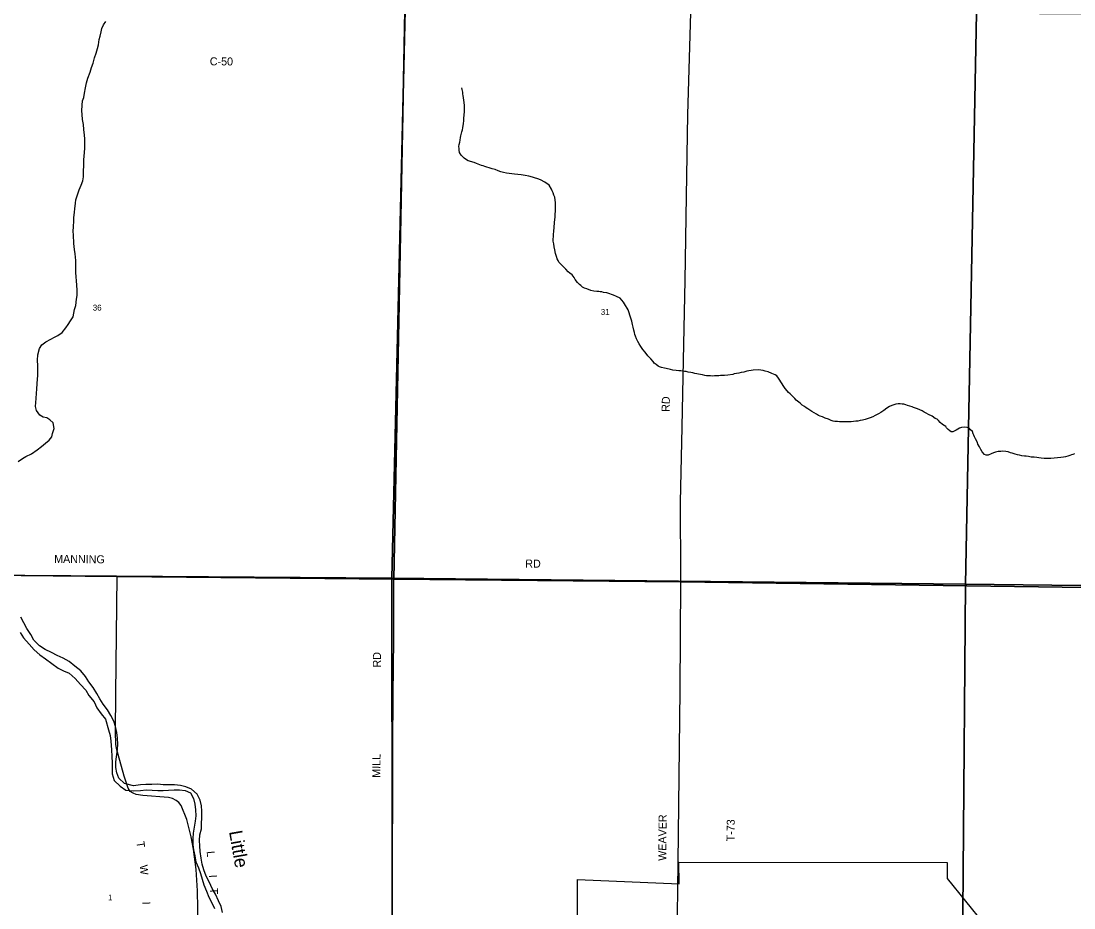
# Model space of a CAD drawing. Extents: x 1312308 to 1684953, y 460642 to 865172.
# Drawn here: x 1439573 to 1449426, y 606234 to 614530 of the extents above; entities that cross this region are included whole.
import ezdxf

# ---------------------------------------------------------------- set-up
doc = ezdxf.new("R2010")
doc.units = 0
for name, color, linetype in [('GM_X_City_Street', 7, 'Continuous'), ('GM_X_Corporation', 7, 'Continuous'), ('GM_X_County_Road', 7, 'Continuous'), ('GM_X_County_Road_Text', 7, 'Continuous'), ('GM_X_Minor_River', 7, 'Continuous'), ('GM_X_Minor_River_Text', 7, 'Continuous'), ('GM_X_Section', 7, 'Continuous'), ('GM_X_Section_Text', 7, 'Continuous'), ('GM_X_Township', 7, 'Continuous'), ('GM_X_Township_Road', 7, 'Continuous'), ('GM_X_Township_Road_Text', 7, 'Continuous')]:
    doc.layers.add(name, color=color, linetype=linetype)

msp = doc.modelspace()

# ---------------------------------------------------------------- linework, layer by layer
at = {"layer": 'GM_X_City_Street'}
msp.add_lwpolyline([(1445695, 601190), (1445690.3, 601641.1), (1445694, 602252.8), (1445695, 602859.2), (1445704.3, 604917.1), (1445707.2, 605261.4), (1445712.1, 605558.2), (1445716.6, 606177.5), (1445719.5, 606404.3), (1445724, 606661.2)], dxfattribs=at)
at = {"layer": 'GM_X_Corporation'}
msp.add_lwpolyline([(1444781.9, 604348.3), (1444781.9, 606501.4), (1445732.6, 606460.3), (1445728.1, 606661.5), (1448239.7, 606658.7), (1448239.7, 606508.7), (1449269.8, 605237)], dxfattribs=at)
at = {"layer": 'GM_X_County_Road'}
for points in [[(1443043.6, 606030.9), (1443047.9, 606430.2), (1443048.8, 606768.8), (1443052.3, 607267), (1443052.3, 607749.7), (1443055.7, 608228.8), (1443060.1, 608745.3), (1443062.5, 609310), (1443164.3, 614625), (1443262.6, 619245.4), (1443279.1, 619936.6), (1443383.2, 625252.4), (1443487.4, 629689.1)], [(1434197.2, 609392.5), (1435199.7, 609380.4), (1437771.4, 609361.5), (1440472, 609335.1), (1443062.5, 609310)], [(1443062.5, 609310), (1445748.3, 609283.3), (1452218.2, 609194.8), (1453789.9, 609169.6)]]:
    msp.add_lwpolyline(points, dxfattribs=at)
at = {"layer": 'GM_X_Minor_River'}
for points in [[(1440169.7, 613427.7), (1440166.4, 613461.8), (1440161.5, 613516.1), (1440156.4, 613562.4), (1440149.4, 613608.7), (1440146.3, 613654.9), (1440141, 613691.1), (1440144.1, 613743.2), (1440148.9, 613783.3), (1440159.6, 613815.2), (1440166.5, 613857.2), (1440177.5, 613905.2), (1440184.5, 613953.2), (1440197.4, 613995.1), (1440218.6, 614050.9), (1440231.5, 614094.9), (1440248.4, 614136.7), (1440261.5, 614186.6), (1440276.4, 614228.5), (1440289.3, 614272.4), (1440296.1, 614308.4), (1440305.1, 614358.4), (1440311.8, 614390.4), (1440322.6, 614428.4), (1440329.3, 614460.4), (1440344, 614494.2), (1440364.7, 614526)], [(1443718, 613614.2), (1443719.1, 613656.4), (1443721.7, 613676.5), (1443722.7, 613716.7), (1443721.3, 613740.9), (1443720, 613767), (1443716.6, 613791.2), (1443713.1, 613813.4), (1443711.6, 613833.6), (1443708, 613847.8), (1443706.4, 613863.9), (1443701, 613890.2), (1443697.4, 613906.3)], [(1445219.1, 611884.9), (1445211.4, 611899.2), (1445180.2, 611938.2), (1445144.4, 611953.1), (1445118.6, 611965.8), (1445098.6, 611972.3), (1445082.7, 611978.7), (1445054.8, 611989.4), (1445024.6, 611992.2), (1445008.7, 611996.6), (1444992.6, 611997), (1444978.5, 611999.3), (1444962.4, 611999.7), (1444932.3, 612002.5), (1444904.4, 612011.2), (1444866.5, 612024.2), (1444846.5, 612030.7), (1444828.7, 612041.2), (1444812.9, 612055.6), (1444799.1, 612066), (1444781.5, 612084.5), (1444760, 612111.2), (1444748.5, 612131.6), (1444731, 612156.1), (1444707.3, 612172.8), (1444693.5, 612185.2), (1444669.9, 612207.8), (1444656.3, 612226.3), (1444642.5, 612236.7), (1444607.2, 612273.7), (1444599.6, 612290), (1444590, 612306.3), (1444582.5, 612328.6), (1444575.2, 612356.9), (1444567.9, 612389.2), (1444560.7, 612419.6), (1444557.4, 612447.8), (1444554, 612472), (1444555.6, 612534.3), (1444558.4, 612564.4), (1444561.3, 612600.5), (1444564.5, 612644.7), (1444569.9, 612698.8), (1444570.7, 612731), (1444573.2, 612747), (1444574.1, 612781.2), (1444574.6, 612801.3), (1444573, 612819.4), (1444573.4, 612833.5), (1444569.9, 612853.7), (1444568.6, 612881.8), (1444559.1, 612902.2), (1444551.6, 612924.5), (1444542, 612942.8), (1444536.4, 612959), (1444515.1, 612993.7), (1444473.6, 613022.9), (1444433.9, 613043.9), (1444408, 613054.6), (1444378.1, 613063.4), (1444358.1, 613069.9), (1444326.1, 613078.7), (1444292.1, 613085.6), (1444254, 613092.5), (1444191.8, 613098.1), (1444165.7, 613100.7), (1444115.5, 613107.9), (1444087.5, 613114.7), (1444063.6, 613121.3), (1444037.6, 613129.9), (1444009.7, 613140.7), (1443981.7, 613147.4), (1443953.8, 613156.1), (1443931.8, 613162.7), (1443913.8, 613169.1), (1443897.9, 613175.5), (1443881.9, 613180), (1443850, 613192.8), (1443836.1, 613197.2), (1443814.1, 613205.7), (1443758.2, 613223.2), (1443740.3, 613231.6), (1443720.6, 613248.2), (1443706.9, 613260.6), (1443693.2, 613275), (1443675.7, 613301.6), (1443672.2, 613321.8), (1443672.6, 613337.8), (1443671.1, 613356), (1443673.6, 613374), (1443678.2, 613396), (1443682.7, 613416), (1443685.4, 613442.1), (1443687.8, 613458.1), (1443696.8, 613494.1), (1443703.4, 613514), (1443707.9, 613532), (1443710.4, 613554.1), (1443712.8, 613568.1), (1443715.7, 613600.2), (1443718, 613614.2)], [(1439546.3, 610409.3), (1439584.9, 610436.7), (1439617.4, 610456.1), (1439670.1, 610481.2), (1439725, 610520.4), (1439765.7, 610549.7), (1439800.5, 610581.2), (1439835.2, 610610.6), (1439859.9, 610642.3), (1439866.5, 610672.2), (1439881.6, 610720.1), (1439874.6, 610772.4), (1439843.1, 610801.1), (1439813.4, 610817.7), (1439779.4, 610826.3), (1439747.7, 610845), (1439718.5, 610887.6), (1439707.2, 610924), (1439712.8, 610998.1), (1439717.8, 611050.2), (1439720.6, 611088.2), (1439723.7, 611140.3), (1439729.3, 611216.5), (1439730.1, 611258.6), (1439729.1, 611304.8), (1439728.1, 611356.9), (1439731.2, 611407.1), (1439746.4, 611467), (1439767.2, 611500.7), (1439803.8, 611528.1), (1439850.5, 611553.3), (1439887, 611574.7), (1439917.4, 611590.2), (1439956.1, 611617.6), (1439991.1, 611659.1), (1440013.8, 611692.8), (1440036.5, 611724.5), (1440059.4, 611764.2), (1440072.8, 611832.1), (1440085.6, 611868), (1440092.9, 611928.1), (1440097.6, 611964.1), (1440098.6, 612014.3), (1440095.5, 612058.5), (1440092.4, 612100.7), (1440089.1, 612138.8), (1440085.9, 612177), (1440085.3, 612245.2), (1440084.2, 612289.4), (1440079.5, 612351.7), (1440072.3, 612394), (1440067.4, 612448.3), (1440063.1, 612530.6), (1440061.7, 612560.7), (1440062.6, 612606.9), (1440065.7, 612657), (1440068.3, 612689), (1440073.4, 612741.1), (1440076.1, 612773.2), (1440081.2, 612827.3), (1440085.9, 612859.3), (1440100.8, 612903.2), (1440115.8, 612951), (1440136.8, 612994.8), (1440151.7, 613036.7), (1440158.4, 613072.7), (1440161.7, 613233.2), (1440167.1, 613299.3), (1440170, 613341.4), (1440170.7, 613379.5), (1440169.7, 613427.7)], [(1447173.3, 610788.3), (1447153.4, 610794.8), (1447129.6, 610807.4), (1447099.6, 610816.2), (1447071.7, 610826.9), (1447051.8, 610835.4), (1447035.8, 610841.8), (1447016, 610852.4), (1446972.4, 610877.6), (1446954.6, 610890.1), (1446934.8, 610902.6), (1446918.9, 610913), (1446903.2, 610925.5), (1446883.4, 610938), (1446863.7, 610954.6), (1446828.2, 610983.6), (1446814.5, 610998), (1446800.7, 611010.4), (1446769.3, 611043.3), (1446755.6, 611055.7), (1446743.9, 611070), (1446724.3, 611092.6), (1446704.9, 611121.2), (1446695.3, 611137.6), (1446683.7, 611155.9), (1446674, 611172.3), (1446660.4, 611190.7), (1446644.9, 611211.2), (1446631, 611219.5), (1446615.1, 611228), (1446599.2, 611234.4), (1446565.3, 611249.3), (1446535.3, 611256), (1446519.3, 611260.4), (1446497.3, 611265), (1446477.2, 611267.5), (1446424.8, 611264.7), (1446364.2, 611254.1), (1446337.8, 611246.7), (1446313.5, 611241.3), (1446291.3, 611237.8), (1446269, 611232.3), (1446246.8, 611228.8), (1446232.6, 611225.2), (1446186.1, 611218.2), (1446155.8, 611214.9), (1446135.7, 611213.4), (1446119.6, 611213.8), (1446103.4, 611212.2), (1446089.4, 611212.5), (1446075.2, 611210.8), (1446061.2, 611211.2), (1446047, 611209.5), (1446024.9, 611210.1), (1446006.8, 611212.5), (1445988.7, 611212.9), (1445972.7, 611215.3), (1445950.7, 611219.9), (1445930.7, 611224.4), (1445912.6, 611226.8), (1445896.6, 611231.2), (1445878.6, 611233.7), (1445860.6, 611238.2), (1445840.6, 611242.7), (1445816.5, 611247.3), (1445796.5, 611251.8), (1445780.4, 611252.2), (1445766.4, 611254.5), (1445746.3, 611257), (1445728.2, 611257.4), (1445702.2, 611262.1), (1445672.1, 611264.8), (1445652.1, 611271.3), (1445638.1, 611273.7), (1445596, 611282.8), (1445568, 611289.5), (1445548.1, 611296), (1445534.2, 611302.3), (1445516.4, 611316.8), (1445498.6, 611329.3), (1445487, 611345.7), (1445465.5, 611370.3), (1445440, 611399.1), (1445412.7, 611431.9), (1445391.3, 611458.6), (1445371.9, 611487.2), (1445358.4, 611509.6), (1445344.9, 611534.1), (1445333.4, 611556.5), (1445322, 611582.9), (1445318.4, 611599.1), (1445312.8, 611617.3), (1445307.4, 611639.5), (1445302, 611665.8), (1445294.7, 611692.1), (1445287.4, 611722.5), (1445280.1, 611750.8), (1445270.7, 611779.2), (1445263.2, 611799.4), (1445253.9, 611829.8), (1445219.1, 611884.9)], [(1449146.9, 610439), (1449120.8, 610441.7), (1449096.7, 610444.3), (1449078.7, 610446.7), (1449054.6, 610449.3), (1449040.5, 610451.7), (1449024.5, 610452), (1449000.4, 610456.7), (1448980.4, 610459.2), (1448964.3, 610461.5), (1448940.2, 610464.1), (1448918.2, 610468.7), (1448898.2, 610473.2), (1448876.2, 610479.8), (1448848.3, 610488.5), (1448832.2, 610490.9), (1448812.3, 610499.4), (1448790.3, 610503.9), (1448762.2, 610506.6), (1448742, 610505.1), (1448715.8, 610503.7), (1448693.5, 610498.2), (1448673.2, 610490.7), (1448652.8, 610481.1), (1448624.4, 610469.8), (1448606.3, 610470.2), (1448588.3, 610476.7), (1448568.8, 610501.2), (1448555.3, 610523.7), (1448543.8, 610546.1), (1448528.4, 610572.6), (1448522.7, 610586.8), (1448503.5, 610623.4), (1448495.9, 610639.7), (1448490.3, 610655.9), (1448482.6, 610670.2), (1448477.1, 610690.4), (1448459.4, 610706.9), (1448445.7, 610721.3), (1448427.7, 610727.8), (1448399.6, 610730.5), (1448373.4, 610727.1), (1448355.1, 610721.5), (1448338.8, 610713.9), (1448324.5, 610704.2), (1448306.1, 610694.6), (1448291.9, 610688.9), (1448277.8, 610689.2), (1448263.9, 610697.6), (1448250.2, 610710), (1448234.4, 610724.4), (1448228.8, 610738.7), (1448197, 610757.5), (1448173.4, 610776.2), (1448159.8, 610794.6), (1448145.9, 610805), (1448128, 610813.5), (1448098.4, 610834.3), (1448064.6, 610849.2), (1448044.8, 610861.7), (1448024.9, 610872.2), (1448007.1, 610882.7), (1447985.2, 610893.3), (1447963.3, 610901.9), (1447943.3, 610908.4), (1447925.4, 610914.8), (1447911.4, 610921.2), (1447869.5, 610934.3), (1447853.6, 610940.7), (1447835.6, 610945.2), (1447819.5, 610947.6), (1447801.5, 610950), (1447781.4, 610950.5), (1447759.1, 610947), (1447740.9, 610941.4), (1447722.6, 610933.8), (1447700.2, 610924.3), (1447675.6, 610908.8), (1447646.9, 610887.4), (1447618.2, 610868), (1447597.8, 610856.4), (1447583.5, 610848.7), (1447567.1, 610839.1), (1447542.7, 610827.6), (1447520.4, 610820.1), (1447500, 610812.5), (1447473.6, 610803.1), (1447447.3, 610797.7), (1447425, 610792.2), (1447402.8, 610788.8), (1447384.7, 610787.2), (1447364.4, 610783.7), (1447342.3, 610782.2), (1447322.1, 610782.7), (1447304, 610781.1), (1447281.9, 610781.6), (1447253.6, 610780.3), (1447231.5, 610780.8), (1447213.5, 610783.3), (1447189.3, 610783.9), (1447173.3, 610788.3)], [(1449431.8, 610480.4), (1449417.5, 610474.7), (1449403.3, 610471), (1449389.1, 610465.3), (1449368.8, 610459.8), (1449348.6, 610454.3), (1449328.3, 610450.7), (1449304.1, 610447.3), (1449273.8, 610444), (1449209.2, 610437.5), (1449146.9, 610439)], [(1440624.7, 607374.8), (1440540.4, 607397.2), (1440487.3, 607448.4), (1440468.3, 607498.9), (1440459.4, 607549.2), (1440460.4, 607599.2), (1440474.8, 607715.1), (1440477.9, 607765.1), (1440477, 607821.2), (1440470.1, 607875.5), (1440455.3, 607931.9), (1440440.3, 607982.3), (1440413.2, 608033), (1440380.3, 608087.8), (1440341.2, 608138.7), (1440310.2, 608189.5), (1440283.2, 608240.2), (1440246.3, 608297), (1440207.2, 608348), (1440176.2, 608398.7), (1440131.2, 608451.8), (1440075.9, 608495.1), (1440022.8, 608540.3), (1439967.2, 608569.5), (1439909.6, 608596.8), (1439858.1, 608624), (1439798.5, 608651.3), (1439745.1, 608686.5), (1439692, 608737.8), (1439663.1, 608792.5), (1439628.2, 608849.4), (1439599.2, 608900.1), (1439572.2, 608954.7)], [(1439563.2, 608810.7), (1439596.3, 608759.9), (1439649.2, 608702.6), (1439694.2, 608649.6), (1439747.4, 608602.3), (1439802.7, 608563.1), (1439862, 608521.7), (1439919.2, 608478.4), (1439970.8, 608453.3), (1440024.5, 608430.1), (1440079.6, 608378.8), (1440130.5, 608323.6), (1440177.6, 608272.5), (1440208.6, 608221.7), (1440257.5, 608162.6), (1440282.4, 608105.9), (1440323.4, 608051), (1440364.4, 608000), (1440390.4, 607899.2), (1440405.4, 607846.8), (1440412.3, 607794.6), (1440418.6, 607712.3), (1440423.4, 607650.1), (1440426.2, 607591.9), (1440425.1, 607541.9), (1440426, 607487.8), (1440444.8, 607427.3), (1440499.8, 607372), (1440553.2, 607334.8), (1440629.8, 607330.9)], [(1441457.9, 606192.1), (1441444.9, 606246.5), (1441421.8, 606301), (1441392.9, 606361.7), (1441361.7, 606414.4), (1441336.7, 606471), (1441305.7, 606531.7), (1441282.8, 606590.3), (1441267.7, 606642.7), (1441258.7, 606699), (1441249.9, 606761.3), (1441244.9, 606813.5), (1441243.8, 606863.6), (1441246.9, 606917.7), (1441260, 606973.6), (1441261, 607023.7), (1441264, 607075.7), (1441265.2, 607139.8), (1441260.1, 607190), (1441249.1, 607242.4), (1441220, 607297), (1441168.7, 607346.1), (1441114.9, 607367.2), (1441064.9, 607378.2), (1441008.8, 607385.3), (1440956.5, 607384.3), (1440902.3, 607385.3), (1440852.2, 607390.3), (1440795.9, 607387.3), (1440741.6, 607388.4), (1440689.9, 607384.5), (1440624.7, 607374.8)], [(1440629.8, 607330.9), (1440690.4, 607333.2), (1440744.7, 607340.2), (1440798.9, 607337.2), (1440853.1, 607332.1), (1440903.3, 607333.2), (1440953.6, 607336.2), (1441005.9, 607339.2), (1441056.1, 607340.3), (1441108.2, 607331.2), (1441160, 607312.2), (1441187.1, 607257.6), (1441200.2, 607205.2), (1441205.1, 607151), (1441208.1, 607096.8), (1441203.1, 607046.8), (1441192, 606990.9), (1441184.9, 606934.9), (1441181.9, 606882.9), (1441180.9, 606828.8), (1441185.9, 606778.6), (1441198.9, 606720.2), (1441209.8, 606663.8), (1441232.9, 606609.3), (1441251.9, 606554.8), (1441267, 606504.4), (1441284.1, 606450), (1441309, 606389.4), (1441330.1, 606334.8), (1441357.2, 606282.2), (1441382.3, 606227.6)]]:
    msp.add_lwpolyline(points, dxfattribs=at)
at = {"layer": 'GM_X_Section'}
for points in [[(1437653.9, 614662.4), (1443168.8, 614630.7), (1443044.1, 609319.5), (1437889.9, 609357.5), (1437782, 609359.8)], [(1443168.8, 614630.7), (1448515.8, 614605.3), (1448412.6, 609263.8), (1443044.1, 609319.5)], [(1448515.8, 614605.3), (1453806.8, 614577.1), (1453800.8, 609199.7), (1448412.6, 609263.8)], [(1437889.9, 609357.5), (1443044.1, 609319.5), (1443050.1, 603939.8), (1443046.7, 603669.9), (1437907.9, 603579.3)], [(1443044.1, 609319.5), (1448412.6, 609263.8), (1448366.6, 603887.1), (1443050.1, 603939.8)], [(1448412.6, 609263.8), (1453800.8, 609199.7), (1453764.9, 603826.9), (1448366.6, 603887.1)]]:
    msp.add_lwpolyline(points, close=True, dxfattribs=at)
at = {"layer": 'GM_X_Township'}
for points in [[(1443487.4, 629689.1), (1443383.2, 625252.4), (1443279.1, 619936.6), (1443262.6, 619245.4), (1443164.3, 614625), (1443062.5, 609310), (1440472, 609335.1), (1437771.4, 609361.5), (1435199.7, 609380.4), (1434197.2, 609392.5), (1430057.8, 609437.8), (1427248.1, 609464.9), (1424759.1, 609498.2), (1422200.5, 609520.2), (1411036.3, 609617.7), (1410999.4, 609618.2), (1411017.8, 611981.1), (1411020.1, 612268.6), (1411090.2, 617032.9), (1411094.7, 617623.7), (1411153.4, 624951), (1411163.3, 625647.7), (1411180.4, 628296.4), (1411210.5, 633565.2)], [(1459184.3, 609129.4), (1453947, 609167.8), (1453828.1, 609169), (1452218.2, 609194.8), (1445748.3, 609283.3), (1443062.5, 609310), (1443164.3, 614625), (1443262.6, 619245.4), (1443279.1, 619936.6), (1443383.2, 625252.4), (1443487.4, 629689.1)], [(1410955.4, 603991.6), (1410977, 606750.9), (1410982, 607392.1), (1410997.9, 609428.6), (1410999.4, 609618.2), (1411036.3, 609617.7), (1422200.5, 609520.2), (1424759.1, 609498.2), (1427248.1, 609464.9), (1430057.8, 609437.8), (1434197.2, 609392.5), (1435199.7, 609380.4), (1437771.4, 609361.5), (1440472, 609335.1), (1443062.5, 609310), (1445748.3, 609283.3), (1452218.2, 609194.8), (1453828.1, 609169), (1453803.6, 608986.7), (1453761.5, 603813.9)]]:
    msp.add_lwpolyline(points, dxfattribs=at)
at = {"layer": 'GM_X_Township_Road'}
for points in [[(1445748, 609336), (1445744.3, 610030.9), (1445760.1, 610730.1), (1445772.3, 611357.4), (1445787.2, 612102.8), (1445801.1, 612892.5), (1445814.4, 613656.3), (1445840.7, 614605.8), (1445852.9, 615266), (1445862.6, 615959.9), (1445872.7, 616666), (1445891.4, 617315.8), (1445893.8, 617950), (1445894.2, 618582.4), (1445908.7, 619222.4), (1445919.7, 619882.8)], [(1441229.9, 606070.9), (1441225.5, 606393.2), (1441211.9, 606594.9), (1441185.5, 606782.3), (1441164.2, 606898.5), (1441122.8, 607060.3), (1441070.1, 607192.8), (1441048.7, 607219.9), (1441025.9, 607239.9), (1440989.6, 607257.7), (1440953.9, 607266.9), (1440712.3, 607286.9), (1440649.6, 607294.7), (1440621.1, 607306.9), (1440594.8, 607324.7), (1440574.1, 607355.3), (1440538.5, 607465.8), (1440465.6, 607724.5), (1440459.6, 607766.7), (1440458.2, 607879.9), (1440458.9, 608238.7), (1440472, 609335.1)], [(1445724, 606661.2), (1445740.4, 608269), (1445748.3, 609283.3), (1445748, 609336)]]:
    msp.add_lwpolyline(points, dxfattribs=at)

# ---------------------------------------------------------------- texts
at = {"layer": 'GM_X_County_Road_Text'}
for s, rotation, p in [('C-50', 359.6571, (1441339, 614116)), ('MANNING', 359.4311, (1439882.5, 609462.1)), ('RD', 359.50635, (1444291.2, 609418)), ('RD', 89.50635, (1442940.2, 608482.7)), ('MILL', 89.72934, (1442935.8, 607451.7))]:
    msp.add_text(s, height=75, rotation=rotation, dxfattribs=at).set_placement(p)
at = {"layer": 'GM_X_Minor_River_Text'}
msp.add_text('Little', height=124.96, rotation=280.0019, dxfattribs=at).set_placement((1441518.4, 606948.4))
at = {"layer": 'GM_X_Section_Text'}
for s, height, p in [('36', 55.25, (1440244.3, 611821.6)), ('31', 55.25, (1444998.5, 611782)), ('1', 55.3, (1440387.3, 606304))]:
    msp.add_text(s, height=height, rotation=0.00001, dxfattribs=at).set_placement(p)
at = {"layer": 'GM_X_Township_Road_Text'}
for s, rotation, p in [('RD', 88.51837, (1445641.8, 610873.9)), ('WEAVER', 89.51713, (1445610.9, 606674.3)), ('T-73', 89.2924, (1446249.6, 606856)), ('T', 278.1489, (1440651.8, 606851.9)), ('L', 275.70719, (1441309.6, 606762.6)), ('W', 274.30344, (1440683, 606635)), ('I', 273.52668, (1441331.7, 606542.3)), ('T', 271.23224, (1441339.1, 606422.5)), ('I', 270.82359, (1440708.9, 606293.2))]:
    msp.add_text(s, height=75, rotation=rotation, dxfattribs=at).set_placement(p)

doc.saveas('drawing.dxf')
